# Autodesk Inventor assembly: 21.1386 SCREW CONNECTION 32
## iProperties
Created: 2006-12
Part Number: 21.1386 SCREW CONNECTION 32
Document SubType Name: Assembly
Designer: Andy Moles
Author: Andy Moles
